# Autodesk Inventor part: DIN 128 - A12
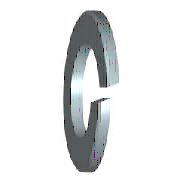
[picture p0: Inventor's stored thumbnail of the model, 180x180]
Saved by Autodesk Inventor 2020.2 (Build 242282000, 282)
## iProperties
Manager: www.cadconsulting.pl
Company: Fabian Stasiak CAD Consulting
Created: 2010-02
Part Number: DIN 128 - A12
Material: Stal, miękka
Description: Podkładka sprężysta
Document SubType Name: Modeling
Standard: DIN 128
Designer: F.Stasiak
Standard Revision: 1994
Standards Organization: DIN
Language: pl-PL
Size Designation: A12
Categories: <MemberInstance><Categories><Category DisplayName="Mocowania" InternalName="e4da775c-781d-43d5-af7c-5136215cf5a6" Mnemonic="FSTN"><Category DisplayName="Podkład
Density: 1 g/cm^3
Appearance: Metal-Stal
IsCustomPart: 0
Author: F.Stasiak
Subject: Zbiór ćwiczeń. Autodesk Inventor 2020. Kurs podstawowy
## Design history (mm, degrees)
sketch "Sketch1"
  geometry: C1 r 10.55 at (0, 0); C2 r 6.35 at (0, 0); 1 further point
  constraints: 2 centre point, 2 coincident
  dimensions: "d0" = 12.7 diameter of C2 (= SD1); "d1" = 21.1 diameter of C1 (= SD2)
extrude "Body" new body sketch "Sketch1" distance "d2" = 2.1 (= SD); taper "d3" = 0 deg
fillet "Fillet" dims "d13" = 1 (= R)
sketch "Sketch2"
  geometry: L1 (0, -6.35)-(0, 6.35) reference; L2 (2.1, 10.55)-(2.1, -10.55) reference; L3 (-1.2, 0)-(7.2, 0) reference; L4 (0, -0.42)-(2.1, 0.792); L5 (0, 0.42)-(2.1, 1.632)
  constraints: 4 end point, 4 point on line, 1 parallel
  dimensions: "d4" = 0.42 distance from line of L3 L4.start (= 0.2 x SD); "d5" = 0.42 distance from line of L3 L5.start (= 0.2 x SD); "d6" = 60 deg angle of L2 L4 (= FAWI)
extrude "Cut" cut sketch "Sketch2" stored distance "d7" = 2.1 (= SD); taper "d8" = 0 deg
workaxis "Work Axis1"
workplane "Work Plane1"
body "Solid1"
other parameters: "SD1" = 12.7 [user parameter; used in 1 equation term], "SD2" = 21.1 [user parameter; used in 1 equation term], "SD" = 2.1 [user parameter; used in 4 equation terms], "FAWI" = 60 deg [user parameter; used in 1 equation term], "d9" = 0, "d10" = 0, "d11" = 0, "d12" = 0, "R" = 1 [user parameter; used in 1 equation term], "NND" = 12 [user parameter]
